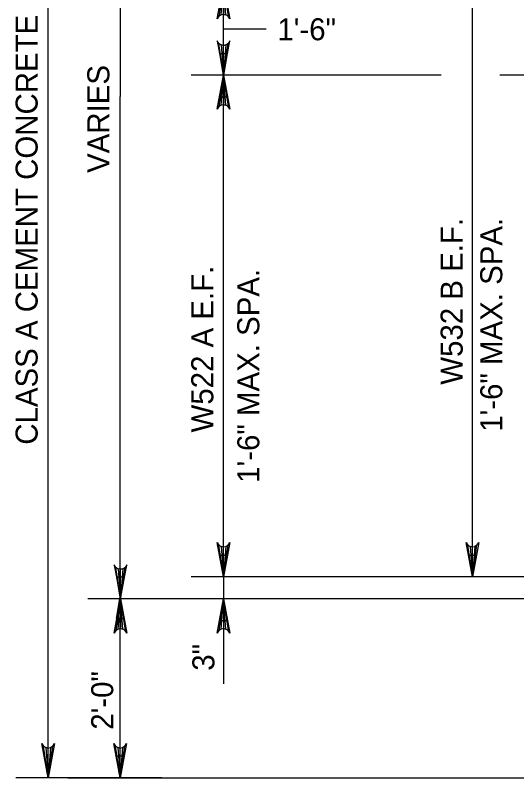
# Model space of a CAD drawing. Extents: x 638255 to 640306, y 296059 to 298435.
# Drawn here: x 638998 to 639066.3, y 296443.1 to 296547.1 of the extents above; entities that cross this region are included whole.
import ezdxf

# ---------------------------------------------------------------- set-up
doc = ezdxf.new("R2010")
doc.units = 0
doc.layers.add('Level 3', color=7, linetype='Continuous')
doc.layers.add('Level 4', color=7, linetype='Continuous')

msp = doc.modelspace()

# ---------------------------------------------------------------- linework, layer by layer
at = {"layer": 'Level 3'}
msp.add_line((639026.34, 296545.23), (639032.16, 296545.23), dxfattribs=at)
at = {"layer": 'Level 4'}
for p, q in [((639002.45, 296443.12), (639002.45, 296604.53)), ((639012.26, 296604.53), (639012.26, 296536.02)), ((639060.24, 296470.53), (639060.24, 296552.61)), ((639026.34, 296541.88), (639026.34, 296548.29)), ((639025.75, 296538.93), (639021.92, 296538.93)), ((639055.98, 296538.93), (639021.92, 296538.93)), ((639026.34, 296470.53), (639026.34, 296538.93)), ((639121.55, 296538.93), (639063.99, 296538.93)), ((639012.26, 296470.45), (639012.26, 296536.02)), ((639083.14, 296470.53), (639021.92, 296470.53)), ((639026.34, 296470.53), (639026.34, 296455.92)), ((639081, 296470.53), (639050.84, 296470.53)), ((639091.21, 296467.51), (639007.84, 296467.51)), ((639057.6, 296467.51), (639021.92, 296467.51)), ((639012.26, 296443.12), (639012.26, 296464.82)), ((639026.34, 296464.56), (639026.34, 296461.61)), ((639017.94, 296443.12), (638998.03, 296443.12)), ((639005.13, 296443.12), (639091.83, 296443.12))]:
    msp.add_line(p, q, dxfattribs=at)
for points in [[(639026.34, 296551.24), (639027.21, 296546.59), (639026.96, 296546.95), (639026.65, 296547.13), (639026.34, 296547.18), (639026.02, 296547.13), (639025.71, 296546.95), (639025.46, 296546.59), (639026.34, 296551.24), (639025.71, 296546.95), (639026.02, 296547.13), (639026.34, 296551.24), (639026.34, 296547.18), (639026.65, 296547.13), (639026.34, 296551.24), (639026.96, 296546.95)], [(639026.34, 296538.93), (639027.21, 296543.58), (639026.96, 296543.22), (639026.65, 296543.04), (639026.34, 296542.98), (639026.02, 296543.04), (639025.71, 296543.22), (639025.46, 296543.58), (639026.34, 296538.93), (639025.71, 296543.22), (639026.02, 296543.04), (639026.34, 296538.93), (639026.34, 296542.98), (639026.65, 296543.04), (639026.34, 296538.93), (639026.96, 296543.22)], [(639026.34, 296538.93), (639027.21, 296534.28), (639026.96, 296534.63), (639026.65, 296534.82), (639026.34, 296534.87), (639026.02, 296534.82), (639025.71, 296534.63), (639025.46, 296534.28), (639026.34, 296538.93), (639025.71, 296534.63), (639026.02, 296534.82), (639026.34, 296538.93), (639026.34, 296534.87), (639026.65, 296534.82), (639026.34, 296538.93), (639026.96, 296534.63)], [(639026.34, 296470.53), (639025.46, 296475.18), (639025.71, 296474.83), (639026.02, 296474.64), (639026.34, 296474.59), (639026.65, 296474.64), (639026.96, 296474.83), (639027.21, 296475.18), (639026.34, 296470.53), (639026.96, 296474.83), (639026.65, 296474.64), (639026.34, 296470.53), (639026.34, 296474.59), (639026.02, 296474.64), (639026.34, 296470.53), (639025.71, 296474.83)], [(639060.24, 296470.53), (639059.37, 296475.18), (639059.61, 296474.83), (639059.93, 296474.64), (639060.24, 296474.59), (639060.55, 296474.64), (639060.86, 296474.83), (639061.11, 296475.18), (639060.24, 296470.53), (639060.86, 296474.83), (639060.55, 296474.64), (639060.24, 296470.53), (639060.24, 296474.59), (639059.93, 296474.64), (639060.24, 296470.53), (639059.61, 296474.83)], [(639012.3, 296467.51), (639013.18, 296472.16), (639012.93, 296471.8), (639012.61, 296471.61), (639012.3, 296471.56), (639011.99, 296471.61), (639011.68, 296471.8), (639011.43, 296472.16), (639012.3, 296467.51), (639011.68, 296471.8), (639011.99, 296471.61), (639012.3, 296467.51), (639012.3, 296471.56), (639012.61, 296471.61), (639012.3, 296467.51), (639012.93, 296471.8)], [(639012.3, 296467.51), (639013.18, 296462.85), (639012.93, 296463.21), (639012.61, 296463.4), (639012.3, 296463.45), (639011.99, 296463.4), (639011.68, 296463.21), (639011.43, 296462.85), (639012.3, 296467.51), (639011.68, 296463.21), (639011.99, 296463.4), (639012.3, 296467.51), (639012.3, 296463.45), (639012.61, 296463.4), (639012.3, 296467.51), (639012.93, 296463.21)], [(639026.34, 296467.51), (639027.21, 296462.85), (639026.96, 296463.21), (639026.65, 296463.4), (639026.34, 296463.45), (639026.02, 296463.4), (639025.71, 296463.21), (639025.46, 296462.85), (639026.34, 296467.51), (639025.71, 296463.21), (639026.02, 296463.4), (639026.34, 296467.51), (639026.34, 296463.45), (639026.65, 296463.4), (639026.34, 296467.51), (639026.96, 296463.21)], [(639002.45, 296443.12), (639001.58, 296447.77), (639001.83, 296447.41), (639002.14, 296447.23), (639002.45, 296447.17), (639002.77, 296447.23), (639003.08, 296447.41), (639003.33, 296447.77), (639002.45, 296443.12), (639003.08, 296447.41), (639002.77, 296447.23), (639002.45, 296443.12), (639002.45, 296447.17), (639002.14, 296447.23), (639002.45, 296443.12), (639001.83, 296447.41)], [(639012.26, 296443.12), (639011.39, 296447.77), (639011.63, 296447.41), (639011.95, 296447.23), (639012.26, 296447.17), (639012.57, 296447.23), (639012.88, 296447.41), (639013.13, 296447.77), (639012.26, 296443.12), (639012.88, 296447.41), (639012.57, 296447.23), (639012.26, 296443.12), (639012.26, 296447.17), (639011.95, 296447.23), (639012.26, 296443.12), (639011.63, 296447.41)]]:
    msp.add_lwpolyline(points, dxfattribs=at)
for points in [[(639025.85, 296541.88), (639026.83, 296541.88), (639026.34, 296538.93)], [(639025.85, 296535.98), (639026.83, 296535.98), (639026.34, 296538.93)], [(639025.85, 296473.48), (639026.83, 296473.48), (639026.34, 296470.53)], [(639059.75, 296473.48), (639060.73, 296473.48), (639060.24, 296470.53)], [(639012.75, 296470.45), (639011.77, 296470.45), (639012.26, 296467.51)], [(639012.75, 296464.82), (639011.77, 296464.82), (639012.26, 296467.77)], [(639025.85, 296464.56), (639026.83, 296464.56), (639026.34, 296467.51)], [(639012.75, 296446.06), (639011.77, 296446.06), (639012.26, 296443.12)]]:
    msp.add_lwpolyline(points, close=True, dxfattribs=at)

# ---------------------------------------------------------------- texts
at = {"layer": 'Level 3'}
for s, p in [('3"', (639025.09, 296457.71)), ('2\'-0"', (639011.31, 296449.67))]:
    msp.add_text(s, height=3, rotation=90, dxfattribs=at).set_placement(p)
at = {"layer": 'Level 4'}
for s, height, p in [('CLASS A CEMENT CONCRETE', 3.0001, (639001.01, 296488.53)), ('VARIES', 3, (639010.78, 296525.59)), ('W532 B E.F.', 3.0001, (639058.91, 296496.71)), ('1\'-6" MAX. SPA.', 3.0001, (639064.31, 296490.3)), ('W522 A E.F.', 3.0001, (639024.94, 296490.2)), ('1\'-6" MAX. SPA.', 3.0001, (639031.21, 296483.34))]:
    msp.add_text(s, height=height, rotation=90, dxfattribs=at).set_placement(p)
msp.add_text('1\'-6"', height=3, dxfattribs=at).set_placement((639033.67, 296543.68))

doc.saveas('drawing.dxf')
